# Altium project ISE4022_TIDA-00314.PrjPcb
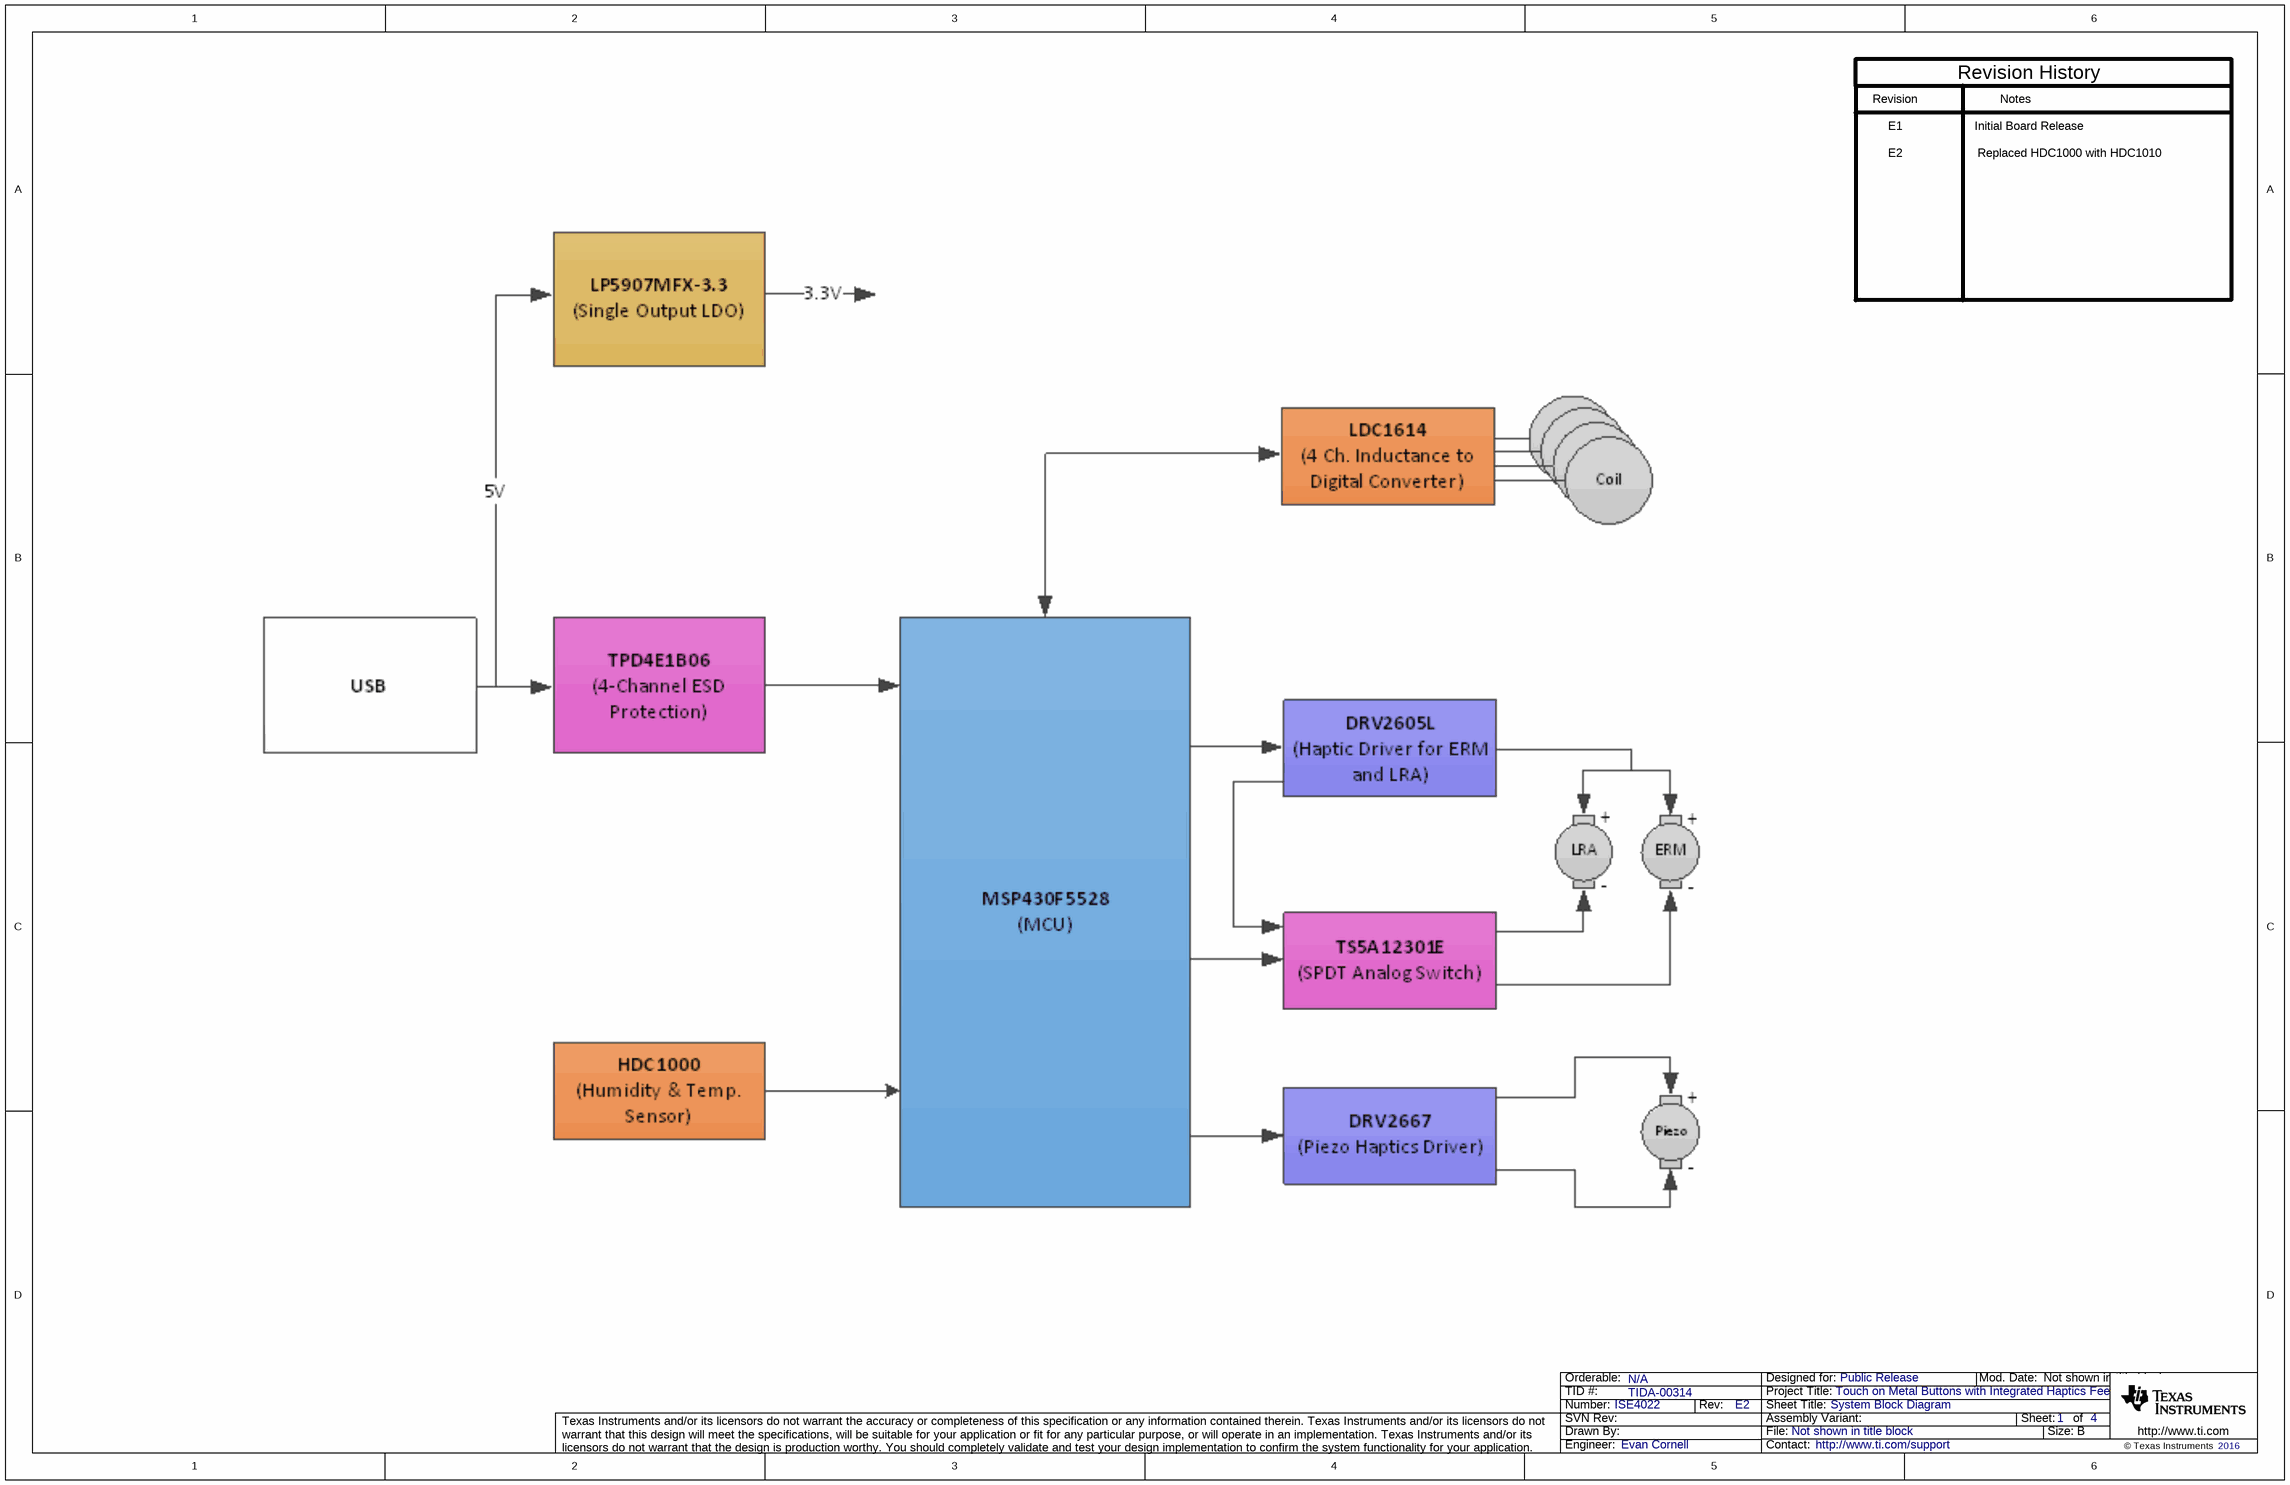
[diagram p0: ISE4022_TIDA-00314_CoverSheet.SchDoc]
TID: TIDA-00314; TechSupport: http://www.ti.com/support; SCH_Rev: E2; PRJ_Title: Touch on Metal Buttons with Integrated Haptics Feedback; PRJ_Number: ISE4022; PRJ_Engineer: Evan Cornell; PRJ_Customer: Public Release; PCB_Rev: E2; PCB_Layout: Krypton Solutions; EVM_Orderable: N/A; CopyrightYear: 2016
4 sheets, 100 parts. Net scope: global (net labels, ports and power ports of the same name join across sheets).
Board file: ISE4022_TIDA-00314_TID.PcbDoc
Sheets:
  ISE4022_TIDA-00314_CoverSheet.SchDoc
  ISE4022_TIDA-00314_MSP430.SchDoc
  ISE4022_TIDA-00314_LDC_Haptics.SchDoc
  ISE4022_TIDA-00314_TID_Hardware.SchDoc

## Sheet ISE4022_TIDA-00314_CoverSheet.SchDoc: System Block Diagram
size 431 x 279 mm; Date: Not shown in title block; ApprovedBy: Not shown in title block; CheckedBy: Not shown in title block; Author: Not shown in title block; CompanyName: Not shown in title block; Engineer: Not shown in title block; Organization: Not shown in title block; Address1: Not shown in title block; Address2: Not shown in title block; Address3: Not shown in title block; Address4: Not shown in title block; DocumentNumber: 1; Revision: Use project parameter SCH_Rev; SheetNumber: 1; SheetTotal: 4; PageSetup: Record=PageOptions¦CenterHorizontal=True¦CenterVertical=True¦PrintScale=1.00¦XCorrection=1.00¦YCorrection=1.00¦PrintKind=0¦BorderSize=5000000¦LeftOffset=0¦BottomOffset=0¦Orientation=2¦PaperLength=1000¦PaperWidth=1000¦Scale=100¦PaperSource=15¦PrintQuality=600¦MediaType=1¦DitherType=10¦PaperKind=Letter¦PrintScaleMode=1

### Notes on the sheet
- Revision
- Notes
- Revision History
- E1
- E2
- Initial Board Release
- Replaced HDC1000 with HDC1010

## Sheet ISE4022_TIDA-00314_MSP430.SchDoc: MSP430
size 431 x 279 mm; Date: Not shown in title block; ApprovedBy: Not shown in title block; CheckedBy: Not shown in title block; Author: Not shown in title block; CompanyName: Not shown in title block; Engineer: Not shown in title block; Organization: Not shown in title block; Address1: Not shown in title block; Address2: Not shown in title block; Address3: Not shown in title block; Address4: Not shown in title block; DocumentNumber: 2; Revision: Use project parameter SCH_Rev; SheetNumber: 2; SheetTotal: 4; PageSetup: Record=PageOptions¦CenterHorizontal=True¦CenterVertical=True¦PrintScale=1.00¦XCorrection=1.00¦YCorrection=1.00¦PrintKind=0¦BorderSize=5000000¦LeftOffset=0¦BottomOffset=0¦Orientation=2¦PaperLength=1000¦PaperWidth=1000¦Scale=100¦PaperSource=15¦PrintQuality=600¦MediaType=1¦DitherType=10¦PaperKind=Letter¦PrintScaleMode=1
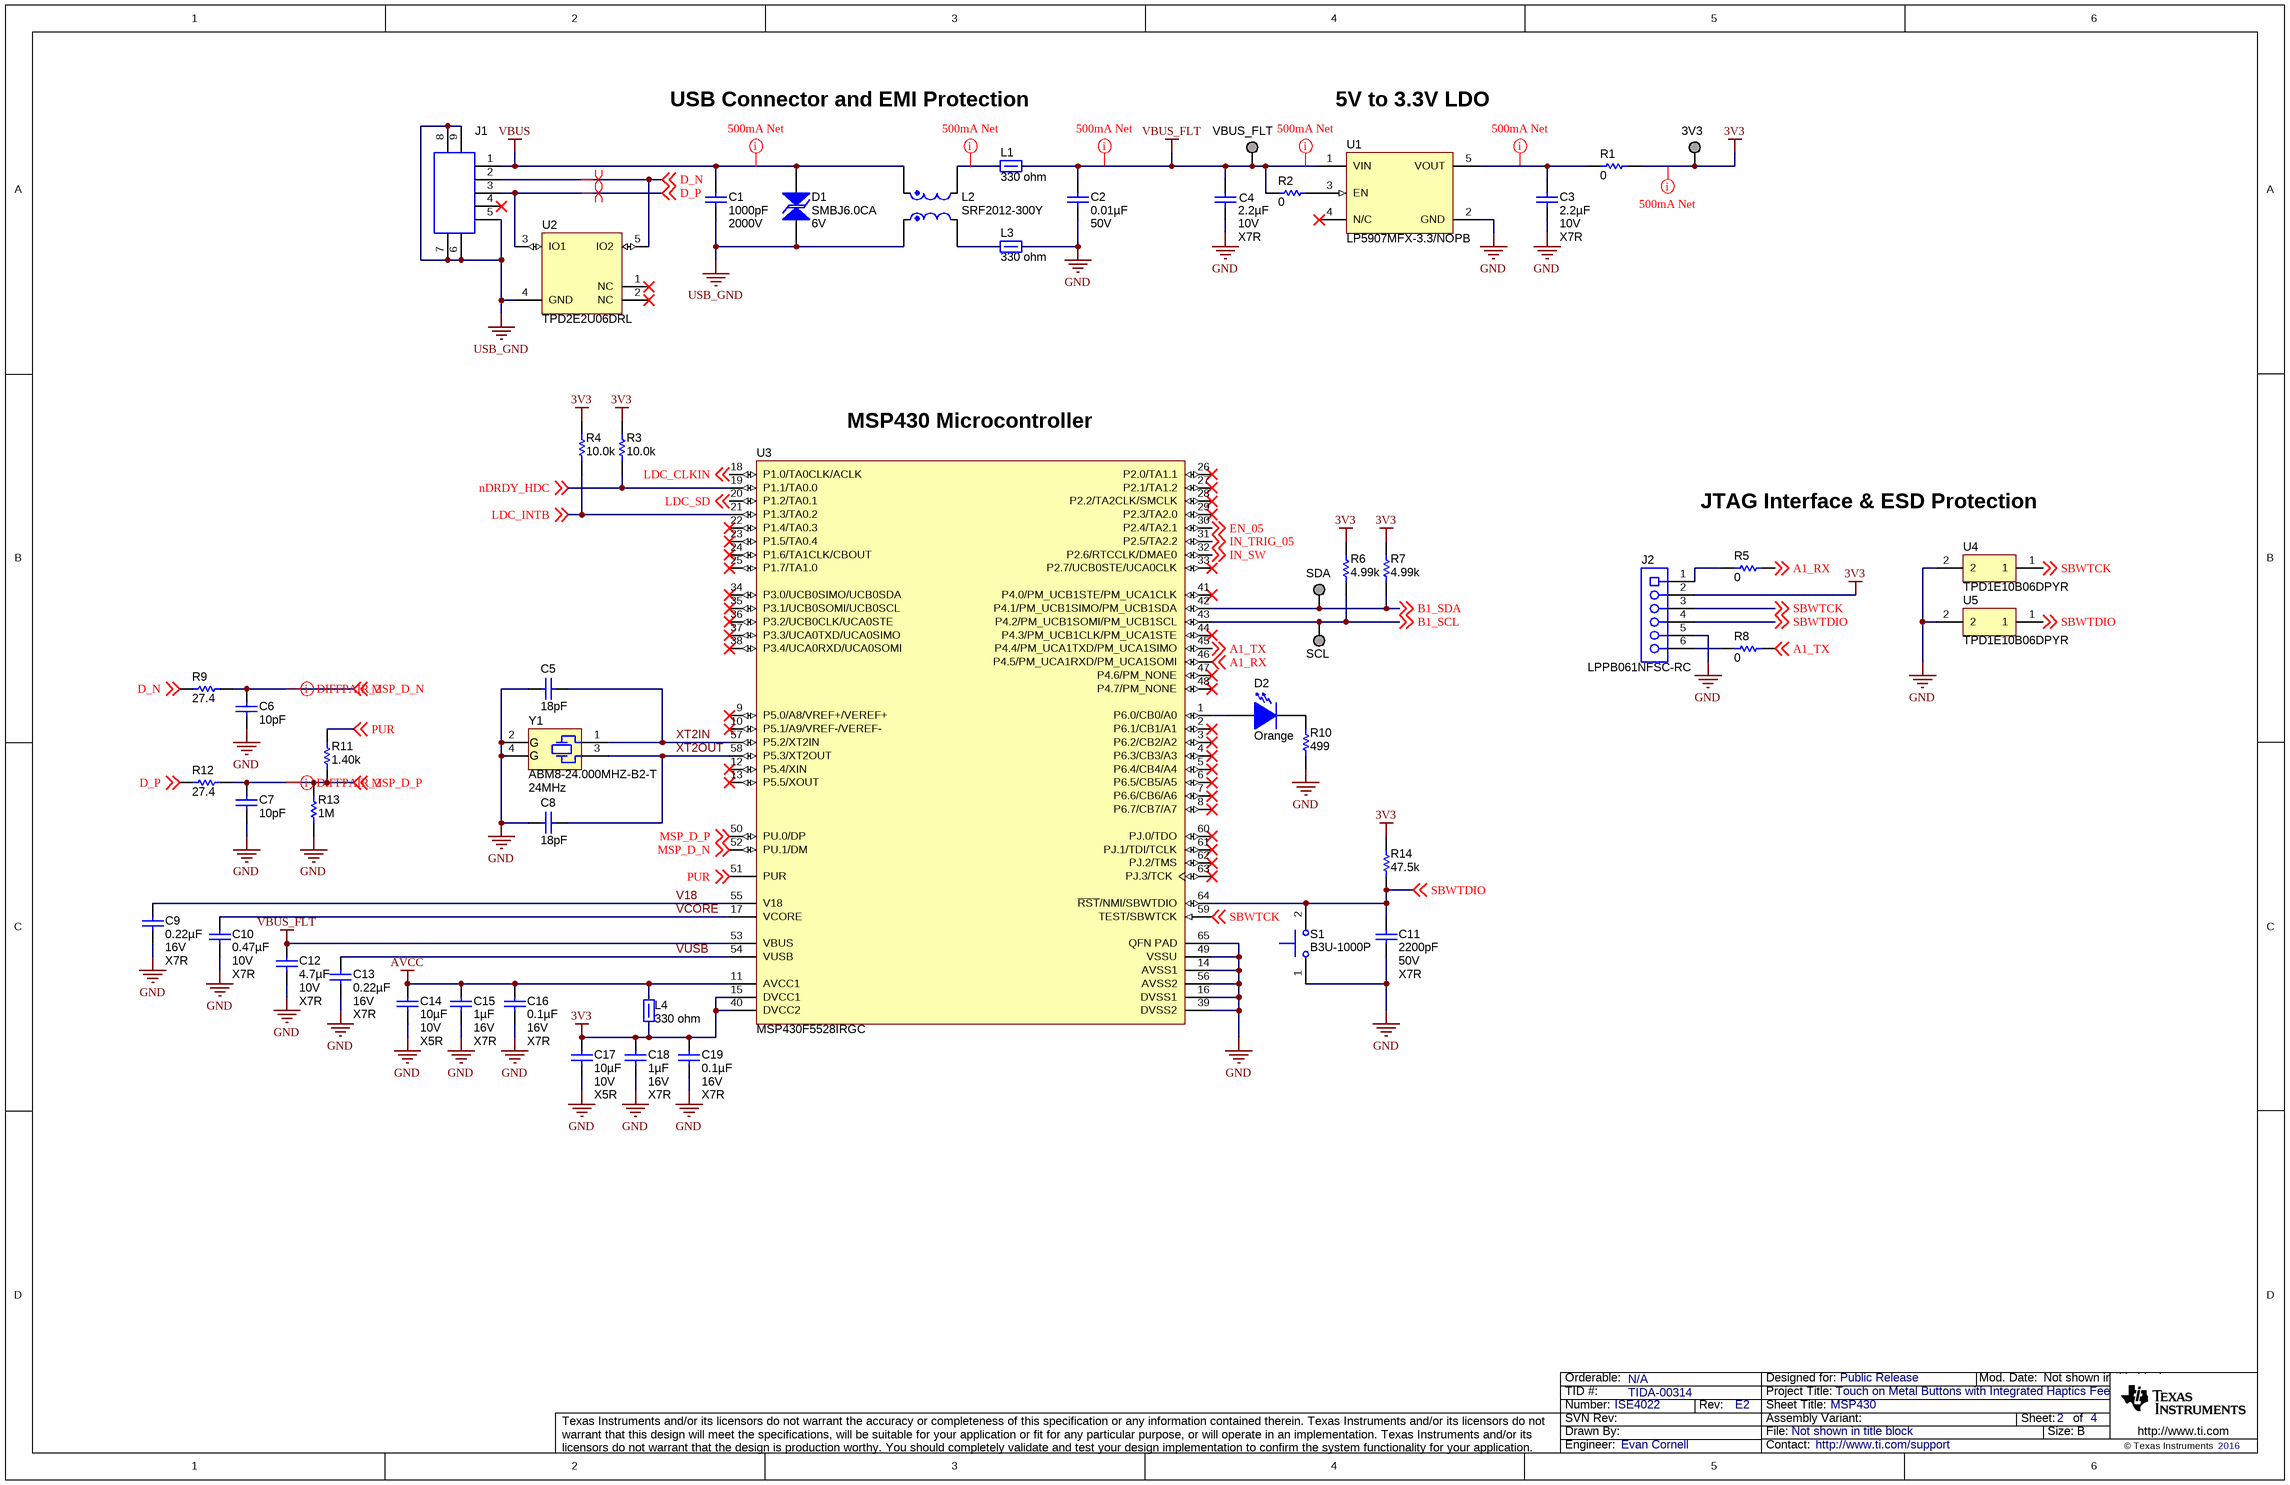
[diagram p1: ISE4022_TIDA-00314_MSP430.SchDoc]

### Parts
3V3  TESTPOINT  [Keystone_5019]  (value not drawn)  (no BOM)
C1  ValueDisplayed: 1000pF  Value2: 2000V  [1210]  (hidden comment: C1210C102KGRACTU)
C2  ValueDisplayed: 0.01µF  Value2: 50V  [0402]  (hidden comment: GCM155R71H103KA55D)
C3  ValueDisplayed: 2.2µF  Value2: 10V  TempCo: X7R  [0603]  (hidden comment: GRM188R71A225KE15D)
C4  ValueDisplayed: 2.2µF  Value2: 10V  TempCo: X7R  [0603]  (hidden comment: GRM188R71A225KE15D)
C5  ValueDisplayed: 18pF  [0603]  (hidden comment: GRM1885C2A180JA01D)
C6  ValueDisplayed: 10pF  [0402]  (hidden comment: 500R07S100JV4T)
C7  ValueDisplayed: 10pF  [0402]  (hidden comment: 500R07S100JV4T)
C8  ValueDisplayed: 18pF  [0603]  (hidden comment: GRM1885C2A180JA01D)
C9  ValueDisplayed: 0.22µF  Value2: 16V  TempCo: X7R  [0402]  (hidden comment: GRM155R71C224KA12D)
C10  ValueDisplayed: 0.47µF  Value2: 10V  TempCo: X7R  [0603]  (hidden comment: C0603C474K8RACTU)
C11  ValueDisplayed: 2200pF  Value2: 50V  TempCo: X7R  [0402]  (hidden comment: C1005X7R1H222K)
C12  ValueDisplayed: 4.7µF  Value2: 10V  TempCo: X7R  [0805_HV]  (hidden comment: GRM21BR71A475KA73L)
C13  ValueDisplayed: 0.22µF  Value2: 16V  TempCo: X7R  [0402]  (hidden comment: GRM155R71C224KA12D)
C14  ValueDisplayed: 10µF  Value2: 10V  TempCo: X5R  [0603]  (hidden comment: C1608X5R1A106M)
C15  ValueDisplayed: 1µF  Value2: 16V  TempCo: X7R  [0603]  (hidden comment: C1608X7R1C105K)
C16  ValueDisplayed: 0.1µF  Value2: 16V  TempCo: X7R  [0402]  (hidden comment: GRM155R71C104KA88D)
C17  ValueDisplayed: 10µF  Value2: 10V  TempCo: X5R  [0603]  (hidden comment: C1608X5R1A106M)
C18  ValueDisplayed: 1µF  Value2: 16V  TempCo: X7R  [0603]  (hidden comment: C1608X7R1C105K)
C19  ValueDisplayed: 0.1µF  Value2: 16V  TempCo: X7R  [0402]  (hidden comment: GRM155R71C104KA88D)
D1  SMBJ6.0CA  value 6V  [SMB]
D2  value Orange  [LED_SMLP12_ORANGE]  (hidden comment: SML-P12DTT86)
J1  651-305-142-821  [CONN_USB-MINI-AB-651-305-142-821]  (value not drawn)
J2  LPPB061NFSC-RC  [Sullins_LPPB061NFSC-RC]
L1  value 330 ohm  [0603]  (hidden comment: BLM18SG331TN1D)
L2  SRF2012-300Y  [SRF2012]
L3  value 330 ohm  [0603]  (hidden comment: BLM18SG331TN1D)
L4  value 330 ohm  [0603]  (hidden comment: BLM18SG331TN1D)
R1  ValueDisplayed: 0  [0805_HV]  (hidden comment: CRCW08050000Z0EA)
R2  value 0  [0402]  (hidden comment: CRCW04020000Z0ED)
R3  ValueDisplayed: 10.0k  [0402]  (hidden comment: CRCW040210K0FKED)
R4  ValueDisplayed: 10.0k  [0402]  (hidden comment: CRCW040210K0FKED)
R5  value 0  [0402]  (hidden comment: CRCW04020000Z0ED)
R6  value 4.99k  [0402]  (hidden comment: CRCW04024K99FKED)
R7  value 4.99k  [0402]  (hidden comment: CRCW04024K99FKED)
R8  value 0  [0402]  (hidden comment: CRCW04020000Z0ED)
R9  ValueDisplayed: 27.4  [0402]  (hidden comment: CRCW040227R4FKED)
R10  ValueDisplayed: 499  [0402]  (hidden comment: CRCW0402499RFKED)
R11  ValueDisplayed: 1.40k  [0402]  (hidden comment: CRCW04021K40FKED)
R12  ValueDisplayed: 27.4  [0402]  (hidden comment: CRCW040227R4FKED)
R13  value 1M  [0402]  (hidden comment: RC0402JR-071ML)
R14  ValueDisplayed: 47.5k  [0402]  (hidden comment: CRCW040247K5FKED)
S1  B3U-1000P  [SW_B3U-1000P]
SCL  TESTPOINT  [Keystone_5019]  (value not drawn)  (no BOM)
SDA  TESTPOINT  [Keystone_5019]  (value not drawn)  (no BOM)
U1  LP5907MFX-3.3/NOPB  [DBV0005A_N]
U2  TPD2E2U06DRL  [DRL0005A]
U3  MSP430F5528IRGC  [RGC0064B]
U4  TPD1E10B06DPYR  [DPY0002A]
U5  TPD1E10B06DPYR  [DPY0002A]
VBUS_FLT  TESTPOINT  [Keystone_5019]  (value not drawn)  (no BOM)
Y1  ABM8-24.000MHZ-B2-T  Frequency: 24MHz  [XTAL_ABM8]

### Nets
3V3: 3V3.1 C17.1 C18.2 C19.2 J2.2 L4.2 R1.2 R3.2 R4.2 R6.2 R7.2 R14.2 U3.15(DVCC1) U3.40(DVCC2)
AVCC: C14.1 C15.2 C16.2 L4.1 U3.11(AVCC1)
GND: C2.2 C3.1 C4.1 C5.1 C6.2 C7.2 C8.1 C9.2 C10.2 C11.1 C12.2 C13.2 C14.2 C15.1 C16.1 C17.2 C18.1 C19.1 J2.5 L3.2 R10.1 R13.1 S1.1 U1.2(GND) U3.14(AVSS1) U3.16(DVSS1) U3.39(DVSS2) U3.49(VSSU) U3.56(AVSS2) U3.65(QFN_PAD) U4.2 U5.2 Y1.2(GND) Y1.4(GND)
USB_GND: C1.2 D1.1 J1.5 J1.6 J1.7 J1.8 J1.9 L2.4 U2.4(GND)
VBUS: C1.1 D1.2 J1.1 L2.1
VBUS_FLT: C2.1 C4.2 C12.1 L1.2 R2.2 U1.1(VIN) U3.53(VBUS) VBUS_FLT.1
A1_RX: R5.1 U3.46(P4.5/PM_UCA1RXD/PM_UCA1SOMI) ; off-sheet A1_RX
A1_TX: R8.1 U3.45(P4.4/PM_UCA1TXD/PM_UCA1SIMO) ; off-sheet A1_TX
B1_SCL: R6.1 SCL.1 U3.43(P4.2/PM_UCB1SOMI/PM_UCB1SCL) ; off-sheet B1_SCL
B1_SDA: R7.1 SDA.1 U3.42(P4.1/PM_UCB1SIMO/PM_UCB1SDA) ; off-sheet B1_SDA
D_N: J1.2 R9.1 U2.5(IO2) ; off-sheet D_N
D_P: J1.3 R12.2 U2.3(IO1) ; off-sheet D_P
EN_05: U3.30(P2.4/TA2.1) ; off-sheet EN_05
IN_SW: U3.32(P2.6/RTCCLK/DMAE0) ; off-sheet IN_SW
IN_TRIG_05: U3.31(P2.5/TA2.2) ; off-sheet IN_TRIG_05
LDC_CLKIN: U3.18(P1.0/TA0CLK/ACLK) ; off-sheet LDC_CLKIN
LDC_INTB: R4.1 U3.21(P1.3/TA0.2) ; off-sheet LDC_INTB
LDC_SD: U3.20(P1.2/TA0.1) ; off-sheet LDC_SD
MSP_D_N: C6.1 R9.2 U3.52(PU.1/DM) ; off-sheet MSP_D_N
MSP_D_P: C7.1 R11.2 R12.1 R13.2 U3.50(PU.0/DP) ; off-sheet MSP_D_P
nDRDY_HDC: R3.1 U3.19(P1.1/TA0.0) ; off-sheet nDRDY_HDC
PUR: R11.1 U3.51(PUR) ; off-sheet PUR
SBWTCK: J2.3 U3.59(TEST/SBWTCK) U4.1 ; off-sheet SBWTCK
SBWTDIO: C11.2 J2.4 R14.1 S1.2 U3.64(~{RST}/NMI/SBWTDIO) U5.1 ; off-sheet SBWTDIO
V18: C9.1 U3.55(V18)
VCORE: C10.1 U3.17(VCORE)
VUSB: C13.1 U3.54(VUSB)
XT2IN: C5.2 U3.57(P5.2/XT2IN) Y1.1
XT2OUT: C8.2 U3.58(P5.3/XT2OUT) Y1.3
NetC3_2: C3.2 R1.1 U1.5(VOUT)
NetD2_1: D2.1(A) U3.1(P6.0/CB0/A0)
NetD2_2: D2.2(K) R10.2
NetJ2_1: J2.1 R5.2
NetJ2_6: J2.6 R8.2
NetL1_1: L1.1 L2.2
NetL2_3: L2.3 L3.1
NetR2_1: R2.1 U1.3(EN)

Not connected (* = marked no-connect by the designer): J1 4*; U1 4(N/C)*; U2 1(NC)* 2(NC)*; U3 2(P6.1/CB1/A1)* 3(P6.2/CB2/A2)* 4(P6.3/CB3/A3)* 5(P6.4/CB4/A4)* 6(P6.5/CB5/A5)* 7(P6.6/CB6/A6)* 8(P6.7/CB7/A7)* 9(P5.0/A8/VREF+/VEREF+)* 10(P5.1/A9/VREF-/VEREF-)* 12(P5.4/XIN)* 13(P5.5/XOUT)* 22(P1.4/TA0.3)* 23(P1.5/TA0.4)* 24(P1.6/TA1CLK/CBOUT)* 25(P1.7/TA1.0)* 26(P2.0/TA1.1)* 27(P2.1/TA1.2)* 28(P2.2/TA2CLK/SMCLK)* 29(P2.3/TA2.0)* 33(P2.7/UCB0STE/UCA0CLK)* 34(P3.0/UCB0SIMO/UCB0SDA)* 35(P3.1/UCB0SOMI/UCB0SCL)* 36(P3.2/UCB0CLK/UCA0STE)* 37(P3.3/UCA0TXD/UCA0SIMO)* 38(P3.4/UCA0RXD/UCA0SOMI)* 41(P4.0/PM_UCB1STE/PM_UCA1CLK)* 44(P4.3/PM_UCB1CLK/PM_UCA1STE)* 47(P4.6/PM_NONE)* 48(P4.7/PM_NONE)* 60(PJ.0/TDO)* 61(PJ.1/TDI/TCLK)* 62(PJ.2/TMS)* 63(PJ.3/TCK)*

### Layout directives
rule Width Constraint [Pref Width = 25mil    Min Width = 5mil    Max Width = 100mil]: 3V3, NetC3_2, NetL1_1, VBUS, VBUS_FLT
differential pair: D_N, D_P, MSP_D_N, MSP_D_P

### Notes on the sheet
- USB Connector and EMI Protection
- 5V to 3.3V LDO
- (near U3) MSP430 Microcontroller
- JTAG Interface & ESD Protection

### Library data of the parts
3V3 SCL SDA VBUS_FLT = 5019: Test Point, Miniature, SMT; Manufacturer: Keystone; CompType: Test Point Loop; U/M: EA
C1 = C1210C102KGRACTU: CAP, CERM, 1000pF, 2000V, +/-10%, X7R, 1210; Manufacturer: Kemet; Polarized: N; CompType: Capacitor; U/M: EA; Cap_F: 0.000000001; Tolerance_%: 10; Value1: Unknown; VDC_V: 2000; TaMin_C: -55; TaMax_C: 125
C2 = GCM155R71H103KA55D: CAP, CERM, 0.01uF, 50V, +/-10%, C0G/NP0, 0402; Manufacturer: MuRata; Polarized: N; CompType: Capacitor; U/M: EA; Cap_F: 0.00000001; Tolerance_%: 10; Value1: Unknown; VDC_V: 50; TaMin_C: -55; TaMax_C: 125
C3 = GRM188R71A225KE15D: CAP, CERM, 2.2 µF, 10 V, +/- 10%, X7R, 0603; Manufacturer: MuRata; Polarized: N; CompType: Capacitor; Value: 2.2uF; U/M: EA; Cap_F: 0.0000022; Tolerance_%: 10; ESR_ohm: 0.009; Value1: 0.009 ohm; TaMin_C: -55; TaMax_C: 125
C4 = GRM188R71A225KE15D: CAP, CERM, 2.2uF, 10V, +/-10%, X7R, 0603; Manufacturer: MuRata; Polarized: N; CompType: Capacitor; U/M: EA; Cap_F: 0.0000022; Tolerance_%: 10; ESR_Ohm: 0.009; Value1: 0.009 ohm; TaMin_C: -55; TaMax_C: 125
C5 C8 = GRM1885C2A180JA01D: CAP, CERM, 18pF, 100V, +/-5%, C0G/NP0, 0603; Manufacturer: MuRata; Polarized: N; CompType: Capacitor; U/M: EA; Cap_F: 0.000000000018; Tolerance_%: 5; Value1: Unknown; VDC_V: 100; TaMin_C: -55; TaMax_C: 125
C6 C7 = 500R07S100JV4T: CAP, CERM, 10 pF, 50 V, +/- 5%, C0G/NP0, 0402; Manufacturer: Johanson Technology; Polarized: N; CompType: Capacitor; Value: 10pF; U/M: EA; Cap_F: 0.00000000001; Tolerance_%: 5; Value1: Unknown; VDC_V: 50; Value2: 50V; TaMin_C: -55; TaMax_C: 125
C9 C13 = GRM155R71C224KA12D: CAP, CERM, 0.22 µF, 16 V, +/- 10%, X7R, 0402; Manufacturer: MuRata; Polarized: N; CompType: Capacitor; Value: 0.22uF; U/M: EA; Cap_F: 0.00000022; Tolerance_%: 10; Value1: Unknown; VDC_V: 16; TaMin_C: -55; TaMax_C: 125
C10 = C0603C474K8RACTU: CAP, CERM, 0.47uF, 10V, +/-10%, X7R, 0603; Manufacturer: Kemet; Polarized: N; CompType: Capacitor; U/M: EA; Cap_F: 0.00000047; Tolerance_%: 10; TaMin_C: -55; TaMax_C: 125
C11 = C1005X7R1H222K: CAP, CERM, 2200 pF, 50 V, +/- 10%, X7R, 0402; Manufacturer: TDK; Polarized: N; CompType: Capacitor; Value: 2200pF; U/M: EA; Cap_F: 0.0000000022; Tolerance_%: 10; ESR_ohm: 0.1433; Value1: 0.1433 ohm; VDC_V: 50; TaMin_C: -55; TaMax_C: 125
C12 = GRM21BR71A475KA73L: CAP, CERM, 4.7 µF, 10 V, +/- 10%, X7R, 0805; Manufacturer: MuRata; Polarized: N; CompType: Capacitor; Value: 4.7uF; U/M: EA; Cap_F: 0.0000047; Tolerance_%: 10; Value1: Unknown; TaMin_C: -55; TaMax_C: 125; Cap_Case: 0805
C14 C17 = C1608X5R1A106M: CAP, CERM, 10 µF, 10 V, +/- 20%, X5R, 0603; Manufacturer: TDK; Polarized: N; CompType: Capacitor; Value: 10uF; U/M: EA; Cap_F: 0.00001; Tolerance_%: 20; ESR_ohm: 0.0078; Value1: 0.0078 ohm; VDC_V: 10; IRMS_A: 1.85; TaMin_C: -55; TaMax_C: 85
C15 = C1608X7R1C105K: CAP, CERM, 1uF, 16V, +/-10%, X7R, 0603; Manufacturer: TDK; Polarized: N; CompType: Capacitor; U/M: EA; Cap_F: 0.000001; Tolerance_%: 10; ESR_Ohm: 0.0057; Value1: 0.0057 ohm; VDC_V: 16; TaMin_C: -55; TaMax_C: 125
C16 = GRM155R71C104KA88D: CAP, CERM, 0.1uF, 16V, +/-10%, X7R, 0402; Manufacturer: MuRata; Polarized: N; CompType: Capacitor; U/M: EA; Cap_F: 0.0000001; Tolerance_%: 10; Value1: Unknown; VDC_V: 16; TaMin_C: -55; TaMax_C: 125
C18 = C1608X7R1C105K: CAP, CERM, 1 µF, 16 V, +/- 10%, X7R, 0603; Manufacturer: TDK; Polarized: N; CompType: Capacitor; Value: 1uF; U/M: EA; Cap_F: 0.000001; Tolerance_%: 10; ESR_ohm: 0.0057; Value1: 0.0057 ohm; VDC_V: 16; TaMin_C: -55; TaMax_C: 125
C19 = GRM155R71C104KA88D: CAP, CERM, 0.1 µF, 16 V, +/- 10%, X7R, 0402; Manufacturer: MuRata; Polarized: N; CompType: Capacitor; Value: 0.1uF; U/M: EA; Cap_F: 0.0000001; Tolerance_%: 10; Value1: Unknown; VDC_V: 16; TaMin_C: -55; TaMax_C: 125
D1 = SMBJ6.0CA: Diode, TVS, Bi, 6 V, 600 W, SMB; Manufacturer: Littelfuse; U/M: EA; Power_W: 600; Vr_V: 6; Value1: 600W; RJA_CperW: 100
D2 = SML-P12DTT86: LED, Orange, SMD; Manufacturer: Rohm; Type: InGaN; Vf_V: 2.1; Value2: 2.1V; Io_A: 0.02; Tjmax_C: 85; Value1: W; U/M: EA
J1 = 651-305-142-821: MINI USB 2.0 SMT TYPE AB 5 CONTACTS R/A, SMD; Manufacturer: Wurth Elektronik eiSos; SymbolCreator: a0799628; CompType: Connector; U/M: EA
J2 = LPPB061NFSC-RC: Receptacle, 1.27mm, 6x1, Gold, SMT; Manufacturer: Sullins Connector Solutions; SymbolCreator: a0411947; U/M: EA
L1 L3 L4 = BLM18SG331TN1D: 1.5A Ferrite Bead, 330 ohm @ 100MHz, SMD; Manufacturer: MuRata; Imax_A: 1.5; DCR_ohm: 0.07; Value1: 0.07 ohm; ZTyp@100MHz_Ohm: 330; U/M: EA
L2 = SRF2012-300Y: Inductor, Wirewound, Ferrite, , 0.45 A, 0.2 ohm, SMD; Manufacturer: Bourns; SymbolCreator: a0411947; Imax_A: 0.45; DCR_ohm: 0.2; Value1: 0.2 ohm; Value2: 0.45A
R1 = CRCW08050000Z0EA: RES, 0, 5%, 0.125 W, 0805; Manufacturer: Vishay-Dale; CompType: Resistor; Value: 0; Value_Code: 0000; Tolerance_%: 5; Power_W: 0.125; Value2: 0.125W; VDC_V: 150; TempCo: 200 ppm/C; EIA_Code: E24; U/M: EA
R2 R5 R8 = CRCW04020000Z0ED: RES, 0 ohm, 5%, 0.063W, 0402; Manufacturer: Vishay-Dale; CompType: Resistor; Value_Code: 0000; Tolerance_%: 5; Power_W: 0.063; VDC_V: 50; TempCo: 200 ppm/C; EIA_Code: E24; U/M: EA
R3 R4 = CRCW040210K0FKED: RES, 10.0 k, 1%, 0.063 W, 0402; Manufacturer: Vishay-Dale; CompType: Resistor; Value: 10.0k; Res_ohm: 10000; Value_Code: 10k0; Tolerance_%: 1; Power_W: 0.063; Value2: 0.063W; VDC_V: 50; TempCo: 100 ppm/C; EIA_Code: E96; U/M: EA
R6 R7 = CRCW04024K99FKED: RES, 4.99k ohm, 1%, 0.063W, 0402; Manufacturer: Vishay-Dale; CompType: Resistor; Res_ohm: 4990; Value_Code: 4k99; Tolerance_%: 1; Power_W: 0.063; VDC_V: 50; TempCo: 100 ppm/C; EIA_Code: E96; U/M: EA
R9 R12 = CRCW040227R4FKED: RES, 27.4, 1%, 0.063 W, 0402; Manufacturer: Vishay-Dale; CompType: Resistor; Value: 27.4; Value_Code: 27R4; Tolerance_%: 1; Power_W: 0.063; Value2: 0.063W; VDC_V: 50; TempCo: 100 ppm/C; EIA_Code: E96; U/M: EA
R10 = CRCW0402499RFKED: RES, 499, 1%, 0.063 W, 0402; Manufacturer: Vishay-Dale; CompType: Resistor; Value: 499; Value_Code: 499R; Tolerance_%: 1; Power_W: 0.063; Value2: 0.063W; VDC_V: 50; TempCo: 100 ppm/C; EIA_Code: E96; U/M: EA
R11 = CRCW04021K40FKED: RES, 1.40 k, 1%, 0.063 W, 0402; Manufacturer: Vishay-Dale; CompType: Resistor; Value: 1.40k; Res_ohm: 1400; Value_Code: 1k40; Tolerance_%: 1; Power_W: 0.063; Value2: 0.063W; VDC_V: 50; TempCo: 100 ppm/C; EIA_Code: E96; U/M: EA
R13 = CRCW040233K0JNED: RES,1M ohm, 5%, 0.063W, 0402; Manufacturer: Yageo; CompType: Resistor; Res_ohm: 33000; Value_Code: 33k0; Tolerance_%: 5; Power_W: 0.063; VDC_V: 50; TempCo: 200 ppm/C; EIA_Code: E24; U/M: EA
R14 = CRCW040247K5FKED: RES, 47.5 k, 1%, 0.063 W, 0402; Manufacturer: Vishay-Dale; CompType: Resistor; Res_ohm: 47500; Value: 47.5k; Value_Code: 47k5; Tolerance_%: 1; Power_W: 0.063; Value2: 0.063W; VDC_V: 50; TempCo: 100 ppm/C; EIA_Code: E96; U/M: EA
S1 = B3U-1000P: SWITCH TACTILE SPST-NO 0.05A 12V; Manufacturer: Omron Electronic Components; SymbolCreator: a0412235; VDC_V: 12; SwitchFunction: Off-Mom; PositionCount: 1; CurrentRating_mA: 50
U1 = LP5907MFX-3.3/NOPB: ULTRA LOW-NOISE, 250-mA LINEAR REGULATOR FOR RF AND ANALOG CIRCUITS REQUIRES NO BYPASS CAPACITOR, DBV0005A; Manufacturer: Texas Instruments; Alternate Manufacturer: None; CompType: IC; SymbolCreator: a0799628; U/M: EA
U2 = TPD2E2U06DRL: DUAL CHANNEL HIGH SPEED ESD PROTECTION DEVICE, DRL0005A; Manufacturer: Texas Instruments; SymbolCreator: a0411947; CompType: IC; U/M: EA
U3 = MSP430F5528IRGC: Mixed Signal MicroController, RGC0064B; Manufacturer: Texas Instruments; ADC: 12-bit SAR; ADC Channels: 16; Brown Out Reset: Yes; DMA: 3; Eco-Plan: Green (RoHS & no Sb/Br); Flash(KB): 128; Frequency(MHz): 25; GPIO: 47; Multiplier: 32x32; SRAM(B): 8192; SubFamily: 5 Series; Timers - 16-bit: 4; USB: 1; USCI_A (UART/LIN/IrDA/SPI): 2; SymbolCreator: Altium/a0412235; CompType: IC; U/M: EA
U4 U5 = TPD1E10B06DPYR: ESD in 0402 Package with 10 pF Capacitance and 6 V Breakdown, 1 Channel, -40 to +125 degC, 2-pin X2SON (DPY), Green (RoHS & no Sb/Br); Manufacturer: Texas Instruments; Alternate Manufacturer: None; Alternate PartNumber: Equivalent; Breakdown Voltage(Min)(V): 6; Eco-Plan: TBD; IEC 61000-4-2 Air-Gap(+/- kV): 30; IO Capacitance(Typ)(pF): 10; SubFamily: ESD Solution
Y1 = ABM8-24.000MHZ-B2-T: Crystal, 24.000MHz, 18pF, SMD; Manufacturer: Abracon Corportation; SymbolCreator: a0412235; U/M: EA; TaMin_C: -20; TaMax_C: 70; Frequency Stability: ±50ppm

## Sheet ISE4022_TIDA-00314_LDC_Haptics.SchDoc: LDC, HDC, & Haptics
size 431 x 279 mm; Date: Not shown in title block; ApprovedBy: Not shown in title block; CheckedBy: Not shown in title block; Author: Not shown in title block; CompanyName: Not shown in title block; Engineer: Not shown in title block; Organization: Not shown in title block; Address1: Not shown in title block; Address2: Not shown in title block; Address3: Not shown in title block; Address4: Not shown in title block; DocumentNumber: 3; Revision: Use project parameter SCH_Rev; SheetNumber: 3; SheetTotal: 4; PageSetup: Record=PageOptions¦CenterHorizontal=True¦CenterVertical=True¦PrintScale=1.00¦XCorrection=1.00¦YCorrection=1.00¦PrintKind=0¦BorderSize=5000000¦LeftOffset=0¦BottomOffset=0¦Orientation=2¦PaperLength=1000¦PaperWidth=1000¦Scale=100¦PaperSource=15¦PrintQuality=600¦MediaType=1¦DitherType=10¦PaperKind=Letter¦PrintScaleMode=1
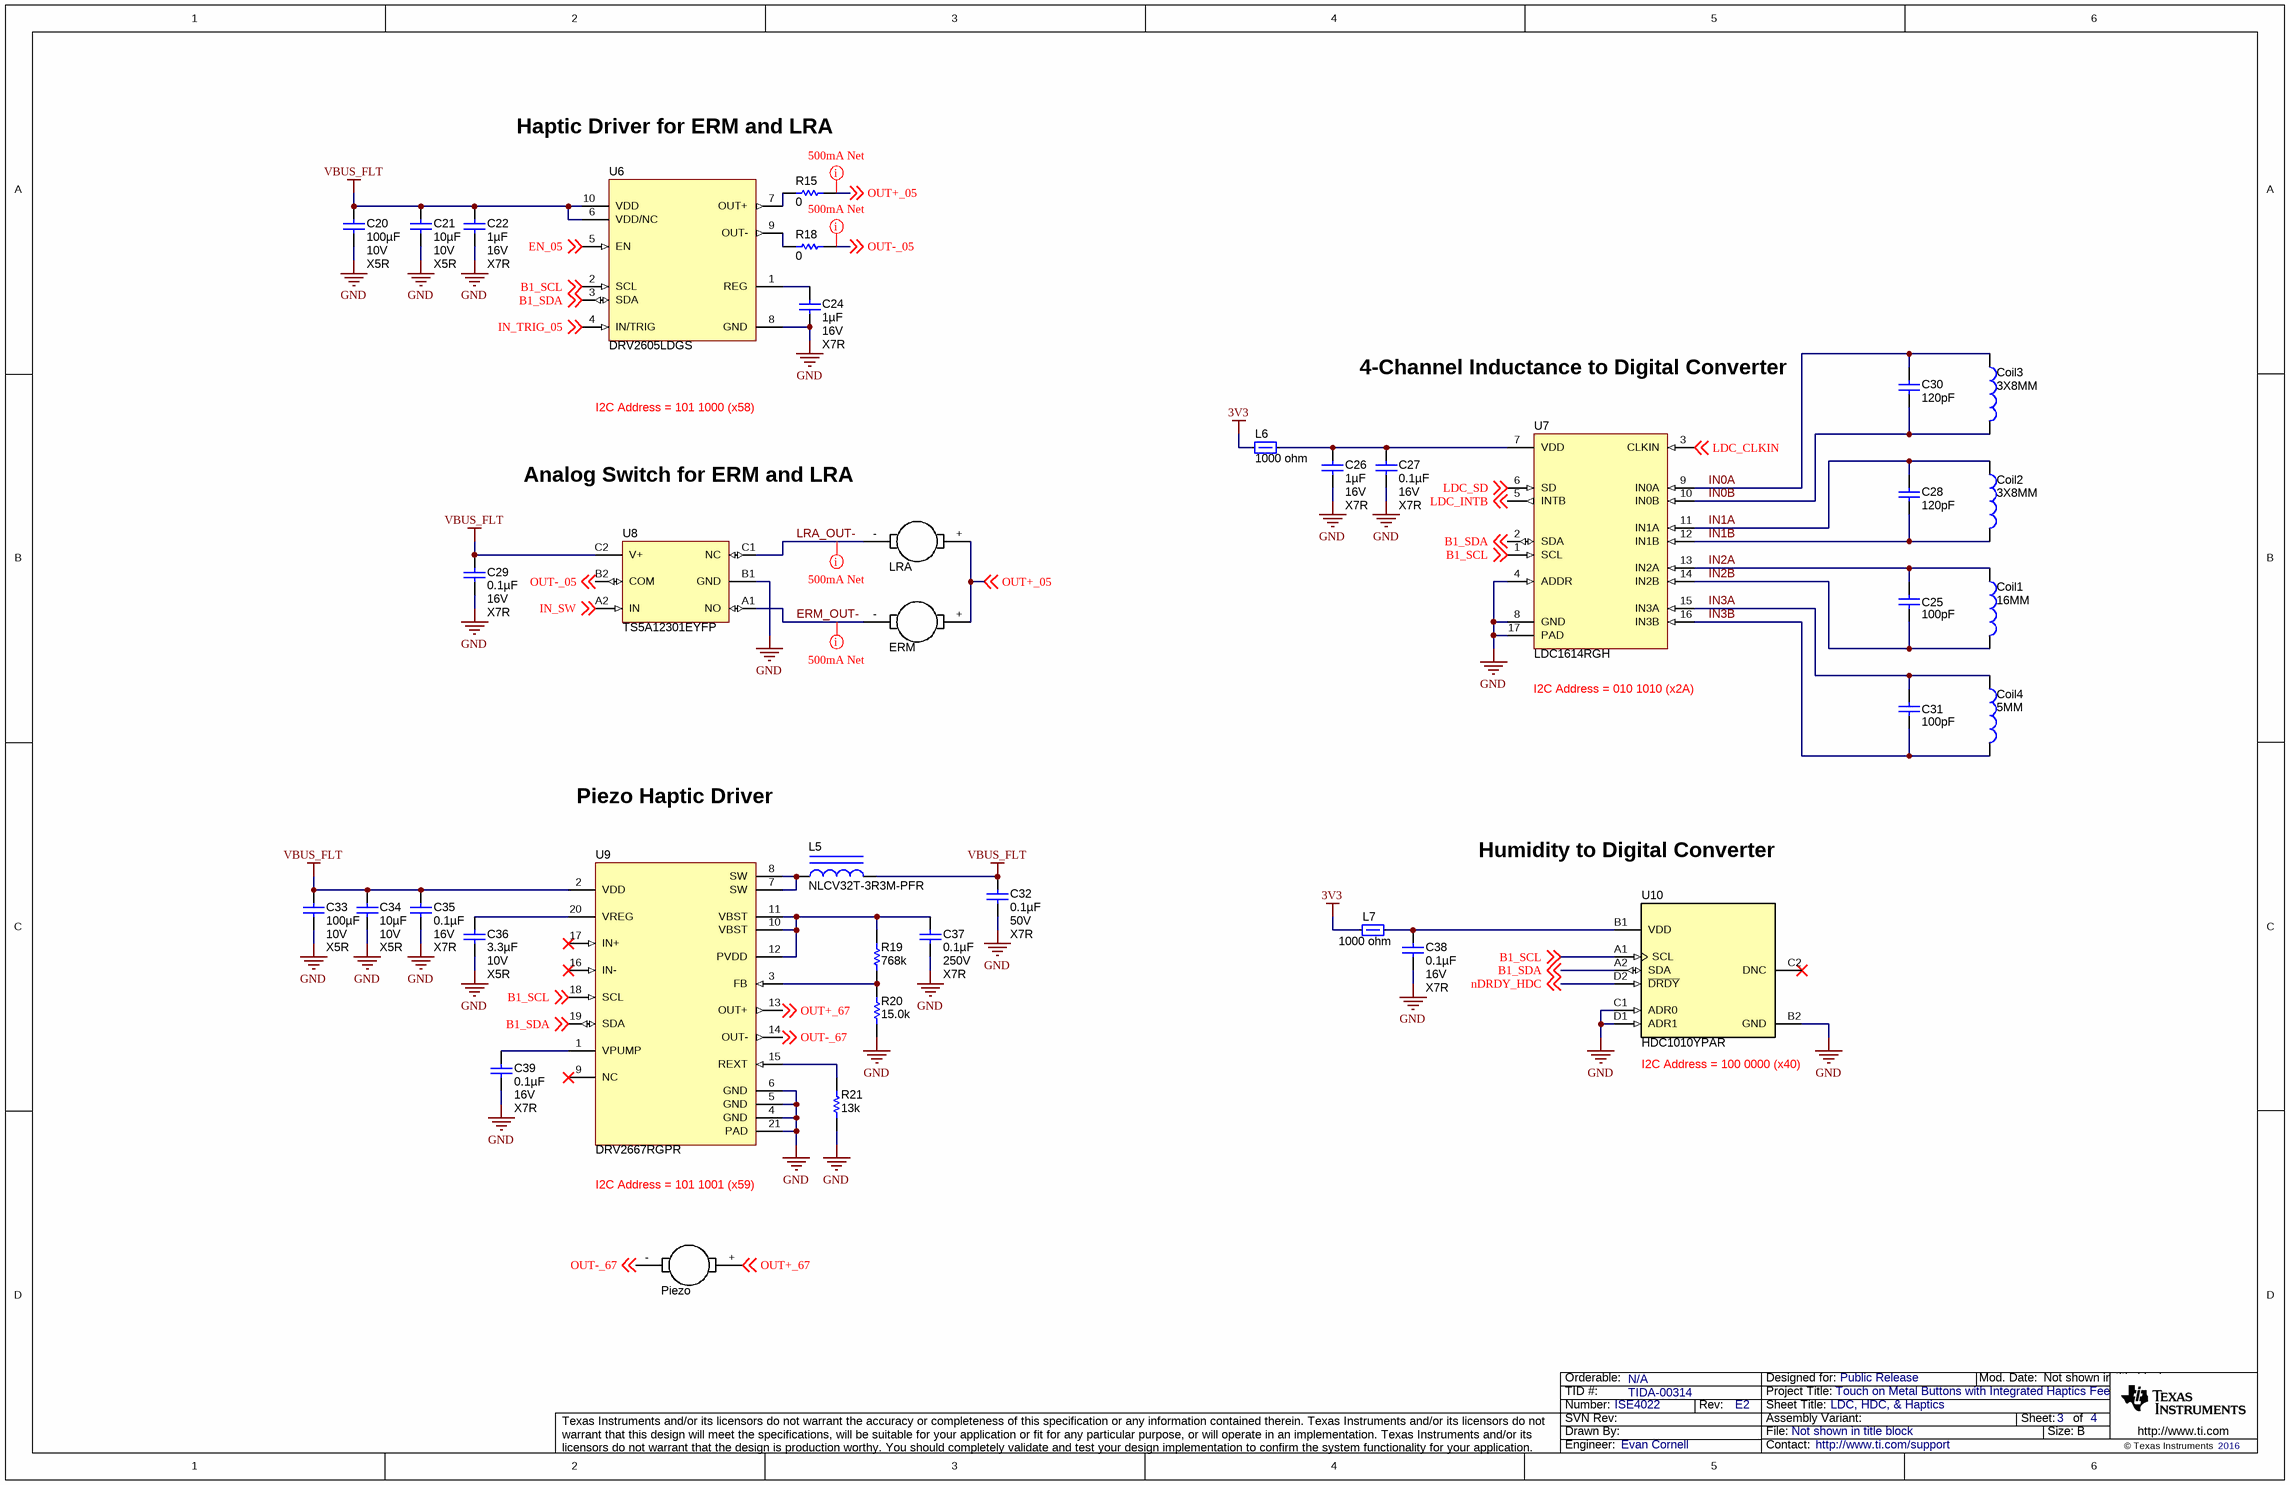
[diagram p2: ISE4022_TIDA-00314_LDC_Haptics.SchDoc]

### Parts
C20  ValueDisplayed: 100µF  Value2: 10V  TempCo: X5R  [1206_190]  (hidden comment: C3216X5R1A107M160AC)
C21  ValueDisplayed: 10µF  Value2: 10V  TempCo: X5R  [0603]  (hidden comment: C1608X5R1A106M)
C22  ValueDisplayed: 1µF  Value2: 16V  TempCo: X7R  [0603]  (hidden comment: C1608X7R1C105K)
C24  ValueDisplayed: 1µF  Value2: 16V  TempCo: X7R  [0603]  (hidden comment: C1608X7R1C105K)
C25  ValueDisplayed: 100pF  [0603]  (hidden comment: 06035A101FAT2A)
C26  ValueDisplayed: 1µF  Value2: 16V  TempCo: X7R  [0603]  (hidden comment: C1608X7R1C105K)
C27  ValueDisplayed: 0.1µF  Value2: 16V  TempCo: X7R  [0402]  (hidden comment: GRM155R71C104KA88D)
C28  ValueDisplayed: 120pF  [0603]  (hidden comment: GRM1885C2A121JA01D)
C29  ValueDisplayed: 0.1µF  Value2: 16V  TempCo: X7R  [0402]  (hidden comment: GRM155R71C104KA88D)
C30  ValueDisplayed: 120pF  [0603]  (hidden comment: GRM1885C2A121JA01D)
C31  ValueDisplayed: 100pF  [0603]  (hidden comment: 06035A101FAT2A)
C32  ValueDisplayed: 0.1µF  Value2: 50V  TempCo: X7R  [0402]  (hidden comment: C1005X7R1H104K050BB)
C33  ValueDisplayed: 100µF  Value2: 10V  TempCo: X5R  [1206_190]  (hidden comment: C3216X5R1A107M160AC)
C34  ValueDisplayed: 10µF  Value2: 10V  TempCo: X5R  [0603]  (hidden comment: C1608X5R1A106M)
C35  ValueDisplayed: 0.1µF  Value2: 16V  TempCo: X7R  [0402]  (hidden comment: GRM155R71C104KA88D)
C36  ValueDisplayed: 3.3µF  Value2: 10V  TempCo: X5R  [0402]  (hidden comment: C1005X5R1A335K050BC)
C37  ValueDisplayed: 0.1µF  Value2: 250V  TempCo: X7R  [1206]  (hidden comment: C3216X7R2E104K)
C38  ValueDisplayed: 0.1µF  Value2: 16V  TempCo: X7R  [0402]  (hidden comment: GRM155R71C104KA88D)
C39  ValueDisplayed: 0.1µF  Value2: 16V  TempCo: X7R  [0402]  (hidden comment: GRM155R71C104KA88D)
Coil1  16MM  [16MMX4]  (net tie, no BOM)
Coil2  3X8MM  [3X8MMX4]  (net tie, no BOM)
Coil3  3X8MM  [3X8MMX4]  (net tie, no BOM)
Coil4  5MM  [5MMX4]  (net tie, no BOM)
ERM  Linear Resonance Actuator  [LRA]  (value not drawn)  (no BOM)
L5  NLCV32T-3R3M-PFR  [NLCV32]
L6  value 1000 ohm  [0603_100]  (hidden comment: 74279266)
L7  value 1000 ohm  [0603_100]  (hidden comment: 74279266)
LRA  Linear Resonance Actuator  [LRA]  (value not drawn)  (no BOM)
Piezo  Linear Resonance Actuator  [LRA]  (value not drawn)  (no BOM)
R15  value 0  [0402]  (hidden comment: CRCW04020000Z0ED)
R18  value 0  [0402]  (hidden comment: CRCW04020000Z0ED)
R19  value 768k  [0402]  (hidden comment: CRCW0402768KFKED)
R20  ValueDisplayed: 15.0k  [0402]  (hidden comment: CRCW040215K0FKED)
R21  value 13k  [0402]  (hidden comment: CRCW040213K0JNED)
U6  DRV2605LDGS  [DGS0010A_N]
U7  LDC1614RGH  [RGH0016A]
U8  TS5A12301EYFP  [YFP0006AAAA]
U9  DRV2667RGPR  [RGP0020D_NV]
U10  HDC1010YPAR  [YPA0008AGAE]

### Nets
3V3: L6.1 L7.2
GND: C20.1 C21.2 C22.1 C24.1 C26.1 C27.1 C29.1 C32.2 C33.1 C34.2 C35.1 C36.1 C37.2 C38.1 C39.1 R20.1 R21.2 U6.8(GND) U7.4(ADDR) U7.8(GND) U7.17(PAD) U8.B1(GND) U9.4(GND) U9.5(GND) U9.6(GND) U9.21(PAD) U10.B2(GND) U10.C1(ADR0) U10.D1(ADR1)
VBUS_FLT: C20.2 C21.1 C22.2 C29.2 C32.1 C33.2 C34.1 C35.2 L5.2 U6.6(VDD/NC) U6.10(VDD) U8.C2(V+) U9.2(VDD)
B1_SCL: U6.2(SCL) U7.1(SCL) U9.18(SCL) U10.A1(SCL) ; off-sheet B1_SCL
B1_SDA: U6.3(SDA) U7.2(SDA) U9.19(SDA) U10.A2(SDA) ; off-sheet B1_SDA
EN_05: U6.5(EN) ; off-sheet EN_05
ERM_OUT-: ERM.- U8.A1(NO)
IN0A: C30.1 Coil3.2 U7.9(IN0A)
IN0B: C30.2 Coil3.1 U7.10(IN0B)
IN1A: C28.1 Coil2.2 U7.11(IN1A)
IN1B: C28.2 Coil2.1 U7.12(IN1B)
IN2A: C25.1 Coil1.2 U7.13(IN2A)
IN2B: C25.2 Coil1.1 U7.14(IN2B)
IN3A: C31.1 Coil4.2 U7.15(IN3A)
IN3B: C31.2 Coil4.1 U7.16(IN3B)
IN_SW: U8.A2(IN) ; off-sheet IN_SW
IN_TRIG_05: U6.4(IN/TRIG) ; off-sheet IN_TRIG_05
LDC_CLKIN: U7.3(CLKIN) ; off-sheet LDC_CLKIN
LDC_INTB: U7.5(INTB) ; off-sheet LDC_INTB
LDC_SD: U7.6(SD) ; off-sheet LDC_SD
LRA_OUT-: LRA.- U8.C1(NC)
nDRDY_HDC: U10.D2(~{DRDY}) ; off-sheet nDRDY_HDC
OUT+_05: ERM.+ LRA.+ R15.2 ; off-sheet OUT+_05
OUT+_67: Piezo.+ U9.13(OUT+) ; off-sheet OUT+_67
OUT-_05: R18.2 U8.B2(COM) ; off-sheet OUT-_05
OUT-_67: Piezo.- U9.14(OUT-) ; off-sheet OUT-_67
NetC24_2: C24.2 U6.1(REG)
NetC26_2: C26.2 C27.2 L6.2 U7.7(VDD)
NetC36_2: C36.2 U9.20(VREG)
NetC37_1: C37.1 R19.2 U9.10(VBST) U9.11(VBST) U9.12(PVDD)
NetC38_2: C38.2 L7.1 U10.B1(VDD)
NetC39_2: C39.2 U9.1(VPUMP)
NetL5_1: L5.1 U9.7(SW) U9.8(SW)
NetR15_1: R15.1 U6.7(OUT+)
NetR18_1: R18.1 U6.9(OUT-)
NetR19_1: R19.1 R20.2 U9.3(FB)
NetR21_1: R21.1 U9.15(REXT)

Not connected (* = marked no-connect by the designer): U9 9(NC)* 16(IN-)* 17(IN+)*; U10 C2(DNC)*

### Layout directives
rule Width Constraint [Pref Width = 25mil    Min Width = 5mil    Max Width = 100mil]: ERM_OUT-, LRA_OUT-, OUT+_05, OUT-_05

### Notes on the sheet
- Haptic Driver for ERM and LRA
- 4-Channel Inductance to Digital Converter
- I2C Address = 101 1000 (x58)
- Analog Switch for ERM and LRA
- (near U7) I2C Address = 010 1010 (x2A)
- Piezo Haptic Driver
- Humidity to Digital Converter
- (near U10) I2C Address = 100 0000 (x40)
- I2C Address = 101 1001 (x59)

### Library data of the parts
C20 C33 = C3216X5R1A107M160AC: CAP, CERM, 100 µF, 10 V, +/- 20%, X5R, 1206_190; Manufacturer: TDK; Polarized: N; CompType: Capacitor; Value: 100uF; U/M: EA; Cap_F: 0.0001; Tolerance_%: 20; Value1: Unknown; VDC_V: 10; TaMin_C: -55; TaMax_C: 85
C21 C34 = C1608X5R1A106M: as C14 on sheet ISE4022_TIDA-00314_MSP430
C22 C24 C26 = C1608X7R1C105K: as C18 on sheet ISE4022_TIDA-00314_MSP430
C25 C31 = GRM1885C2A300JA01D: CAP CER 100PF 50V 1% NP0 0603; Manufacturer: AVX Corporation; Polarized: N; CompType: Capacitor; U/M: EA; Cap_F: 0.00000000003; Tolerance_%: 5; VDC_V: 100; Value2: 100V; TempCo: C0G/NP0; TaMin_C: -55; TaMax_C: 125
C27 C29 C38 C39 = GRM155R71C104KA88D: as C19 on sheet ISE4022_TIDA-00314_MSP430
C28 C30 = GRM1885C2A121JA01D: CAP, CERM, 120 pF, 100 V, +/- 5%, C0G/NP0, 0603; Manufacturer: MuRata; Polarized: N; CompType: Capacitor; Value: 120pF; U/M: EA; Cap_F: 0.00000000012; Tolerance_%: 5; Value1: Unknown; VDC_V: 100; Value2: 100V; TaMin_C: -55; TaMax_C: 125
C32 = C1005X7R1H104K050BB: CAP, CERM, 0.1 µF, 50 V, +/- 10%, X7R, 0402; Manufacturer: TDK; Polarized: N; CompType: Capacitor; Value: 0.1uF; U/M: EA; Cap_F: 0.0000001; Tolerance_%: 10; Value1: Unknown; VDC_V: 50; TaMin_C: -55; TaMax_C: 125
C35 = GRM155R71C104KA88D: as C16 on sheet ISE4022_TIDA-00314_MSP430
C36 = C1005X5R1A335K050BC: CAP, CERM, 3.3 µF, 10 V, +/- 10%, X5R, 0402; Manufacturer: TDK; Polarized: N; CompType: Capacitor; Value: 3.3uF; U/M: EA; Cap_F: 0.0000033; Tolerance_%: 10; Value1: Unknown; TaMin_C: -55; TaMax_C: 85
C37 = C3216X7R2E104K: CAP, CERM, 0.1uF, 250V, +/-10%, X7R, 1206; Manufacturer: TDK; Polarized: N; CompType: Capacitor; U/M: EA; Cap_F: 0.0000001; Tolerance_%: 10; ESR_Ohm: 0.0217; Value1: 0.0217 ohm; VDC_V: 250; TaMin_C: -55; TaMax_C: 125
Coil1-Coil4 = Inductor: Inductor, [Technology], [Material], xxuH, xxA, x.xx ohm, [MountType]; Manufacturer: Used in BOM report; U/M: EA
ERM LRA Piezo = LRA: Manufacturer: Used in BOM report; SymbolVersion: use current date i.e. 2008-05-20; SymbolCreator: Use a-id; CompType: Used in some BOM reports.  Useful for finding later.; U/M: EA, IN, or GM
L5 = NLCV32T-3R3M-PFR: Inductor, Wirewound, Ferrite, 3.3uH, 1A, 0.16 ohm, SMD; Manufacturer: TDK; Ind_H: 3.3E-6; ValueDisplayed: 3.3µH; Imax_A: 1; Irms: 1A @ 20C rise; Isat: 1A @ 10% inductance drop; DCR_ohm: 0.16
L6 L7 = 74279266: Ferrite Bead, 1000 ohm @ 100 MHz, 0.2 A, 0603; Manufacturer: Wurth Elektronik eiSos; Imax_A: 0.2; DCR_ohm: 0.6; Value1: 0.6 ohm; Value2: 0.2A; ZTyp@100MHz_Ohm: 1000
R15 R18 = CRCW04020000Z0ED: as R2 on sheet ISE4022_TIDA-00314_MSP430
R19 = CRCW0402768KFKED: RES, 768k ohm, 1%, 0.063W, 0402; Manufacturer: Vishay-Dale; CompType: Resistor; Res_ohm: 768000; Tolerance_%: 1; Power_W: 0.063; VDC_V: 50; TempCo: 100 ppm/C; EIA_Code: E96; U/M: EA
R20 = CRCW040215K0FKED: RES, 15.0 k, 1%, 0.063 W, 0402; Manufacturer: Vishay-Dale; CompType: Resistor; Res_ohm: 15000; Value: 15.0k; Value_Code: 15k0; Tolerance_%: 1; Power_W: 0.063; Value2: 0.063W; VDC_V: 50; TempCo: 100 ppm/C; EIA_Code: E96; U/M: EA
R21 = CRCW040213K0JNED: RES, 13k ohm, 5%, 0.063W, 0402; Manufacturer: Vishay-Dale; CompType: Resistor; Res_ohm: 13000; Value_Code: 13k0; Tolerance_%: 5; Power_W: 0.063; VDC_V: 50; TempCo: 200 ppm/C; EIA_Code: E24; U/M: EA
U6 = DRV2605LDGS: Haptic Driver for LRA and ERM With Built-In Library and Smart Loop Architecture, DGS0010A; Manufacturer: Texas Instruments; SymbolCreator: a0411947; CompType: IC; U/M: EA
U7 = LDC1614RGH: Multi-Channel 12/28-Bit Inductance to Digital Converter with I2C, RGH0016A; Manufacturer: Texas Instruments; SymbolCreator: a0411947; CompType: IC; U/M: EA
U8 = TS5A12301EYFP: IEC LEVEL 4 ESD-PROTECTED 0.75-O SPDT ANALOG SWITCH WITH 1.8-V COMPATIBLE INPUT LOGIC, YFP0006AAAA; Alternate Manufacturer: None; Manufacturer: Texas Instruments; SymbolCreator: a0411947; CompType: IC; U/M: EA
U9 = DRV2667RGPR: Piezo Haptic Driver with Boost, Digital Front End, and Internal Waveform Memory, RGP0020D; Alternate Manufacturer: Texas Instruments; Alternate PartNumber: DRV2667RGPT; SymbolCreator: a0412235; CompType: IC; U/M: EA
U10 = HDC1010YPAR: Low Power, High Accuracy Digital Humidity Sensor with Temperature Sensor, YPA0008AGAE; Alternate PartNumber: HDC1010YPAT; Manufacturer: Texas Instruments; SymbolCreator: Altium; CompType: IC; U/M: EA; SizeX_mm: 1.59; SizeY_mm: 2.04; SizeZ_mm: 0.675

## Sheet ISE4022_TIDA-00314_TID_Hardware.SchDoc: Hardware
size 431 x 279 mm; Date: Not shown in title block; ApprovedBy: Not shown in title block; CheckedBy: Not shown in title block; Author: Not shown in title block; CompanyName: Not shown in title block; Engineer: Not shown in title block; Organization: Not shown in title block; Address1: Not shown in title block; Address2: Not shown in title block; Address3: Not shown in title block; Address4: Not shown in title block; DocumentNumber: 4; Revision: Use project parameter SCH_Rev; SheetNumber: 4; SheetTotal: 4; PageSetup: Record=PageOptions¦CenterHorizontal=True¦CenterVertical=True¦PrintScale=1.00¦XCorrection=1.00¦YCorrection=1.00¦PrintKind=0¦BorderSize=5000000¦LeftOffset=0¦BottomOffset=0¦Orientation=2¦PaperLength=1000¦PaperWidth=1000¦Scale=100¦PaperSource=15¦PrintQuality=600¦MediaType=1¦DitherType=10¦PaperKind=Letter¦PrintScaleMode=1
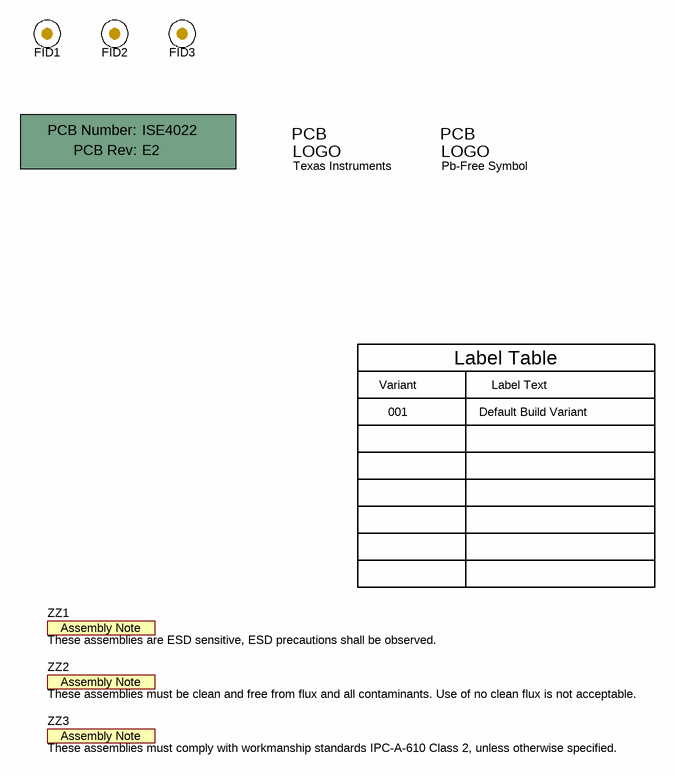
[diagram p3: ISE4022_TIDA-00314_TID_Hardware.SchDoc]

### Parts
!PCB1  Printed Circuit Board  (value not drawn)  (mechanical)
FID1  Fiducial  [Fiducial10-20]  (value not drawn)
FID2  Fiducial  [Fiducial10-20]  (value not drawn)
FID3  Fiducial  [Fiducial10-20]  (value not drawn)
Logo1  Texas Instruments  [TI_Stacked_Overlay_Small]  (no BOM)
Logo2  Pb-Free Symbol  [Pb-Free_Overlay_Small]  (no BOM)
ZZ1  These assemblies are ESD sensitive, ESD precautions shall be observed.  [AssemblyNote]  (no BOM)
ZZ2  These assemblies must be clean and free from flux and all contaminants. Use of no clean flux is not acceptable.  [AssemblyNote]  (no BOM)
ZZ3  These assemblies must comply with workmanship standards IPC-A-610 Class 2, unless otherwise specified.  [AssemblyNote]  (no BOM)

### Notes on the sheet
- Variant
- Label Table
- Label Text
- 001
- Default Build Variant

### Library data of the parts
!PCB1 = PCB: Manufacturer: Any; PartNumber: ISE4022; SymbolCreator: a0412235
FID1-FID3 = Fiducial: Fiducial mark.  There is nothing to buy or mount.; SymbolCreator: codlsc
Logo1 = TI_Logo: Texas Instrument Corporate Signature; SymbolCreator: codlsc
Logo2 = Pb-Free: SymbolCreator: a0412235
ZZ1-ZZ3 = AssemblyNote: SymbolCreator: codlsc

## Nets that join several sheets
3V3: ISE4022_TIDA-00314_MSP430 (14 pins), ISE4022_TIDA-00314_LDC_Haptics (L6.1 L7.2)
GND: ISE4022_TIDA-00314_MSP430 (34 pins), ISE4022_TIDA-00314_LDC_Haptics (29 pins)
VBUS_FLT: ISE4022_TIDA-00314_MSP430 (8 pins), ISE4022_TIDA-00314_LDC_Haptics (13 pins)
B1_SCL: ISE4022_TIDA-00314_MSP430 (R6.1 SCL.1 U3.43), ISE4022_TIDA-00314_LDC_Haptics (U6.2 U7.1 U9.18 U10.A1)
B1_SDA: ISE4022_TIDA-00314_MSP430 (R7.1 SDA.1 U3.42), ISE4022_TIDA-00314_LDC_Haptics (U6.3 U7.2 U9.19 U10.A2)
EN_05: ISE4022_TIDA-00314_MSP430 (U3.30), ISE4022_TIDA-00314_LDC_Haptics (U6.5)
IN_SW: ISE4022_TIDA-00314_MSP430 (U3.32), ISE4022_TIDA-00314_LDC_Haptics (U8.A2)
IN_TRIG_05: ISE4022_TIDA-00314_MSP430 (U3.31), ISE4022_TIDA-00314_LDC_Haptics (U6.4)
LDC_CLKIN: ISE4022_TIDA-00314_MSP430 (U3.18), ISE4022_TIDA-00314_LDC_Haptics (U7.3)
LDC_INTB: ISE4022_TIDA-00314_MSP430 (R4.1 U3.21), ISE4022_TIDA-00314_LDC_Haptics (U7.5)
LDC_SD: ISE4022_TIDA-00314_MSP430 (U3.20), ISE4022_TIDA-00314_LDC_Haptics (U7.6)
nDRDY_HDC: ISE4022_TIDA-00314_MSP430 (R3.1 U3.19), ISE4022_TIDA-00314_LDC_Haptics (U10.D2)

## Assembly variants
001: not fitted C20 C33 ERM FID1 FID2 FID3 LRA Piezo R3 R4 ZZ1 ZZ2 ZZ3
